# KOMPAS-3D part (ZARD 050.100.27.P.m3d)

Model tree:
1. Булева операция:1
2. Булева операция:2
3. Булева операция:3
4. Булева операция:4
5. Булева операция:5
6. Булева операция:6
7. Булева операция:7
8. Булева операция:8
9. Булева операция:9
10. Булева операция:10
11. Булева операция:11
12. Булева операция:12
13. Булева операция:13
14. Булева операция:14
15. Булева операция:15
16. Булева операция:16
17. Булева операция:17
18. Булева операция:18
19. Булева операция:19
20. Булева операция:20
21. Булева операция:21
22. Булева операция:22

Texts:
  ООО ИК Энерпред-Ярдос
